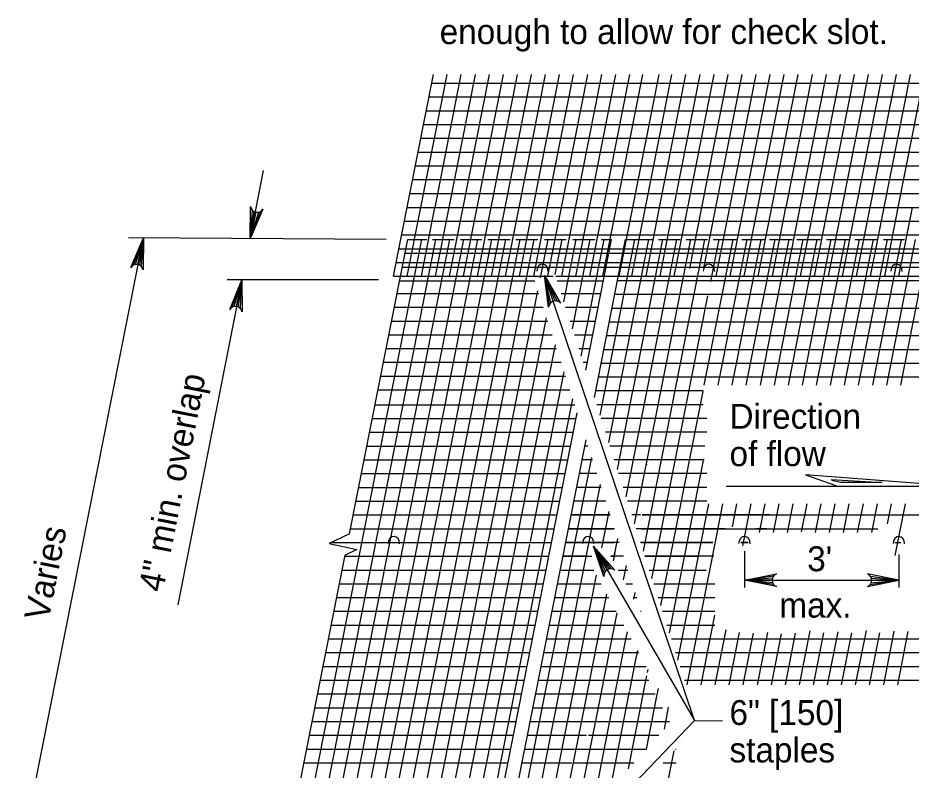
# Model space of a CAD drawing. Extents: x 1083.1 to 1117.1, y 719.4 to 741.4.
# Drawn here: x 1096.26 to 1101.28, y 728.46 to 732.68 of the extents above; entities that cross this region are included whole.
import ezdxf

# ---------------------------------------------------------------- set-up
doc = ezdxf.new("R2010")
doc.units = 0
doc.layers.add('ST_Details', color=7, linetype='Continuous')
doc.layers.add('ST_Text', color=7, linetype='Continuous')

msp = doc.modelspace()

# ---------------------------------------------------------------- linework, layer by layer
at = {"layer": 'ST_Details'}
for p, q in [((1098.3754, 731.2305), (1098.5998, 732.3652)), ((1098.5294, 731.6174), (1098.6773, 732.3652)), ((1098.6083, 731.6174), (1098.7562, 732.3652)), ((1098.6872, 731.6174), (1098.835, 732.3652)), ((1098.7661, 731.6174), (1098.9139, 732.3652)), ((1098.8449, 731.6174), (1098.9928, 732.3652)), ((1098.9238, 731.6174), (1099.0717, 732.3652)), ((1099.0027, 731.6174), (1099.1505, 732.3652)), ((1099.0816, 731.6174), (1099.2294, 732.3652)), ((1099.1604, 731.6174), (1099.3083, 732.3652)), ((1099.2393, 731.6174), (1099.3872, 732.3652)), ((1099.3183, 731.6174), (1099.4661, 732.3652)), ((1099.3971, 731.6174), (1099.5449, 732.3652)), ((1099.476, 731.6174), (1099.6238, 732.3652)), ((1099.5548, 731.6174), (1099.7027, 732.3652)), ((1099.6273, 731.6174), (1099.7752, 732.3652)), ((1099.7191, 731.6174), (1099.8669, 732.3652)), ((1099.7915, 731.6174), (1099.9394, 732.3652)), ((1099.8703, 731.6174), (1100.0183, 732.3652)), ((1099.9493, 731.6174), (1100.0971, 732.3652)), ((1100.0281, 731.6174), (1100.176, 732.3652)), ((1100.107, 731.6174), (1100.2548, 732.3652)), ((1100.1859, 731.6174), (1100.3338, 732.3652)), ((1100.2648, 731.6174), (1100.4126, 732.3652)), ((1100.3437, 731.6174), (1100.4915, 732.3652)), ((1100.4225, 731.6174), (1100.5703, 732.3652)), ((1100.5014, 731.6174), (1100.6493, 732.3652)), ((1100.5803, 731.6174), (1100.7282, 732.3652)), ((1100.6592, 731.6174), (1100.807, 732.3652)), ((1100.738, 731.6174), (1100.8859, 732.3652)), ((1100.8169, 731.6174), (1100.9648, 732.3652)), ((1100.8958, 731.6174), (1101.0437, 732.3652)), ((1100.9747, 731.6174), (1101.1225, 732.3652)), ((1101.0536, 731.6174), (1101.2014, 732.3652)), ((1101.1324, 731.6174), (1101.2803, 732.3652)), ((1101.2113, 731.6174), (1101.3592, 732.3652)), ((1101.9012, 732.3137), (1098.5898, 732.3137)), ((1101.8858, 732.2363), (1098.5745, 732.2363)), ((1101.8706, 732.159), (1098.5592, 732.159)), ((1101.8553, 732.0816), (1098.5439, 732.0816)), ((1101.8399, 732.0042), (1098.5286, 732.0042)), ((1101.8247, 731.9269), (1098.5133, 731.9269)), ((1101.8093, 731.8495), (1098.498, 731.8495)), ((1097.5708, 731.4497), (1097.645, 731.8248)), ((1101.7941, 731.7722), (1098.4827, 731.7722)), ((1101.7788, 731.6947), (1098.4673, 731.6947)), ((1097.5808, 731.6032), (1097.5693, 731.4418)), ((1098.4518, 731.6174), (1101.7633, 731.6174)), ((1098.452, 731.6174), (1099.6343, 731.6174)), ((1098.4528, 731.2305), (1098.5293, 731.6174)), ((1098.5317, 731.2305), (1098.6082, 731.6174)), ((1098.6106, 731.2305), (1098.687, 731.6174)), ((1098.6894, 731.2305), (1098.7659, 731.6174)), ((1098.7683, 731.2305), (1098.8448, 731.6174)), ((1098.8472, 731.2305), (1098.9237, 731.6174)), ((1098.9261, 731.2305), (1099.0025, 731.6174)), ((1099.0049, 731.2305), (1099.0814, 731.6174)), ((1099.0838, 731.2305), (1099.1603, 731.6174)), ((1099.1627, 731.2305), (1099.2392, 731.6174)), ((1099.2416, 731.2305), (1099.3181, 731.6174)), ((1099.3205, 731.2305), (1099.3969, 731.6174)), ((1099.3993, 731.2305), (1099.4758, 731.6174)), ((1099.4783, 731.2305), (1099.5547, 731.6174)), ((1099.5507, 731.2305), (1099.6272, 731.6174)), ((1099.6425, 731.2305), (1099.7189, 731.6174)), ((1099.7148, 731.2305), (1099.7913, 731.6174)), ((1099.7938, 731.2305), (1099.8702, 731.6174)), ((1099.8726, 731.2305), (1099.9491, 731.6174)), ((1099.9515, 731.2305), (1100.028, 731.6174)), ((1100.0392, 731.275), (1100.1068, 731.6174)), ((1100.1183, 731.2763), (1100.1858, 731.6174)), ((1100.1882, 731.2305), (1100.2646, 731.6174)), ((1100.267, 731.2305), (1100.3435, 731.6174)), ((1100.3459, 731.2305), (1100.4223, 731.6174)), ((1100.4248, 731.2305), (1100.5013, 731.6174)), ((1100.5037, 731.2305), (1100.5801, 731.6174)), ((1100.5825, 731.2305), (1100.659, 731.6174)), ((1100.6614, 731.2305), (1100.7378, 731.6174)), ((1100.7403, 731.2305), (1100.8168, 731.6174)), ((1100.8192, 731.2305), (1100.8957, 731.6174)), ((1100.8981, 731.2305), (1100.9745, 731.6174)), ((1100.9769, 731.2305), (1101.0534, 731.6174)), ((1101.0558, 731.2305), (1101.1323, 731.6174)), ((1101.1347, 731.2305), (1101.2112, 731.6174)), ((1101.2136, 731.2305), (1101.29, 731.6174)), ((1097.5905, 731.5956), (1097.5693, 731.4418)), ((1097.6273, 731.5952), (1097.5693, 731.4418)), ((1097.6013, 731.5916), (1097.5693, 731.4418)), ((1097.6159, 731.5913), (1097.5693, 731.4418)), ((1098.4365, 731.54), (1101.748, 731.54)), ((1098.4368, 731.54), (1099.6189, 731.54)), ((1096.2648, 727.8872), (1096.9698, 731.4464)), ((1098.3344, 731.4372), (1096.8864, 731.4464)), ((1096.9135, 731.2932), (1096.9712, 731.4467)), ((1096.9249, 731.2971), (1096.9712, 731.4467)), ((1096.9396, 731.2969), (1096.9712, 731.4467)), ((1096.9503, 731.2929), (1096.9712, 731.4467)), ((1096.96, 731.2853), (1096.9712, 731.4467)), ((1098.4213, 731.4627), (1101.7328, 731.4627)), ((1098.4214, 731.4627), (1099.6036, 731.4627)), ((1097.8295, 727.8781), (1098.5338, 731.4372)), ((1097.9083, 727.8781), (1098.6126, 731.4372)), ((1097.9873, 727.8781), (1098.6915, 731.4372)), ((1098.0662, 727.8781), (1098.7704, 731.4372)), ((1098.128, 729.7837), (1098.4548, 731.4372)), ((1098.145, 727.8781), (1098.8493, 731.4372)), ((1098.2239, 727.8781), (1098.9282, 731.4372)), ((1098.3028, 727.8781), (1099.007, 731.4372)), ((1098.3817, 727.8781), (1099.0859, 731.4372)), ((1098.4548, 731.4372), (1098.5617, 731.4372)), ((1098.4605, 727.8781), (1099.1648, 731.4372)), ((1098.5943, 731.4372), (1098.7153, 731.4372)), ((1098.7523, 731.4372), (1098.8722, 731.4372)), ((1098.906, 731.4372), (1099.031, 731.4372)), ((1099.0629, 731.4372), (1099.1868, 731.4372)), ((1099.2011, 731.2221), (1099.2437, 731.4372)), ((1099.2242, 731.4372), (1099.3446, 731.4372)), ((1099.2837, 731.2407), (1099.3225, 731.4372)), ((1099.3323, 731.088), (1099.4014, 731.4372)), ((1099.381, 730.9349), (1099.4803, 731.4372)), ((1099.3828, 731.4372), (1099.5073, 731.4372)), ((1099.4298, 730.7821), (1099.5592, 731.4372)), ((1099.4551, 730.7024), (1099.6003, 731.4372)), ((1099.5038, 730.5496), (1099.6792, 731.4372)), ((1099.5354, 730.45), (1099.7306, 731.4372)), ((1099.5416, 731.4372), (1099.6003, 731.4372)), ((1099.5841, 730.2972), (1099.8095, 731.4372)), ((1099.6792, 731.4372), (1099.8299, 731.4372)), ((1099.6814, 729.9917), (1099.9673, 731.4372)), ((1099.7191, 730.5807), (1099.8884, 731.4372)), ((1099.8635, 731.4372), (1099.9853, 731.4372)), ((1099.9089, 730.7417), (1100.0462, 731.4372)), ((1100.019, 731.4372), (1100.1399, 731.4372)), ((1100.09, 731.2597), (1100.1251, 731.4372)), ((1100.1208, 730.618), (1100.2827, 731.4372)), ((1100.1573, 731.2008), (1100.204, 731.4372)), ((1100.171, 731.4372), (1100.3024, 731.4372)), ((1100.1996, 730.618), (1100.3616, 731.4372)), ((1100.2785, 730.618), (1100.4404, 731.4372)), ((1100.3327, 731.4372), (1100.4604, 731.4372)), ((1100.3573, 730.618), (1100.5193, 731.4372)), ((1100.4363, 730.618), (1100.5982, 731.4372)), ((1100.4881, 731.4372), (1100.6176, 731.4372)), ((1100.5151, 730.618), (1100.6771, 731.4372)), ((1100.5941, 730.618), (1100.7559, 731.4372)), ((1100.6409, 731.4372), (1100.7742, 731.4372)), ((1100.6729, 730.618), (1100.8348, 731.4372)), ((1100.7518, 730.618), (1100.9137, 731.4372)), ((1100.8069, 731.4372), (1100.9337, 731.4372)), ((1100.8307, 730.618), (1100.9926, 731.4372)), ((1100.9095, 730.618), (1101.0715, 731.4372)), ((1100.967, 731.4372), (1101.0923, 731.4372)), ((1100.9884, 730.618), (1101.1503, 731.4372)), ((1101.0673, 730.618), (1101.2293, 731.4372)), ((1101.1273, 731.4372), (1101.2462, 731.4372)), ((1101.1462, 730.618), (1101.3081, 731.4372)), ((1101.225, 730.618), (1101.387, 731.4372)), ((1098.406, 731.3852), (1101.7174, 731.3852)), ((1098.4061, 731.3852), (1099.5883, 731.3852)), ((1098.4395, 731.3598), (1102.2394, 731.3598)), ((1098.3908, 731.3079), (1099.5729, 731.3079)), ((1098.3908, 731.3079), (1101.7022, 731.3079)), ((1098.4243, 731.2825), (1102.2241, 731.2825)), ((1099.7788, 729.6857), (1100.0908, 731.2637)), ((1097.5238, 731.2114), (1097.1626, 729.3849)), ((1098.2907, 731.2114), (1097.4404, 731.2114)), ((1097.468, 731.0572), (1097.5238, 731.2114)), ((1097.4793, 731.0612), (1097.5238, 731.2114)), ((1097.494, 731.0612), (1097.5238, 731.2114)), ((1097.5048, 731.0574), (1097.5238, 731.2114)), ((1097.5147, 731.0499), (1097.5238, 731.2114)), ((1098.3754, 731.2305), (1099.2724, 731.2305)), ((1098.409, 731.2052), (1099.1688, 731.2052)), ((1100.0671, 728.734), (1099.2233, 731.2357)), ((1099.2725, 731.0907), (1099.2233, 731.2357)), ((1099.2598, 731.0834), (1099.2233, 731.2357)), ((1099.2519, 731.0742), (1099.2233, 731.2357)), ((1099.2838, 731.0927), (1099.2233, 731.2357)), ((1099.296, 731.0912), (1099.2233, 731.2357)), ((1099.2869, 731.2305), (1101.7658, 731.2305)), ((1099.295, 731.2052), (1099.5549, 731.2052)), ((1100.1537, 731.2052), (1099.6333, 731.2052)), ((1102.2088, 731.2052), (1100.1558, 731.2052)), ((1098.5394, 727.8781), (1099.1867, 731.1494)), ((1098.395, 731.1341), (1099.1917, 731.1341)), ((1099.3177, 731.1341), (1099.5404, 731.1341)), ((1099.5404, 731.1341), (1099.5404, 731.1341)), ((1100.1454, 731.1277), (1099.618, 731.1277)), ((1099.8274, 729.5331), (1100.1413, 731.1202)), ((1102.1935, 731.1277), (1100.1454, 731.1277)), ((1098.3797, 731.0567), (1099.2166, 731.0567)), ((1099.3423, 731.0567), (1099.5252, 731.0567)), ((1100.0889, 731.0504), (1099.6027, 731.0504)), ((1102.1782, 731.0504), (1100.0889, 731.0504)), ((1098.6183, 727.8781), (1099.2356, 730.9977)), ((1099.8875, 731.0337), (1099.8875, 731.0338)), ((1098.3643, 730.9793), (1099.2415, 730.9793)), ((1099.3669, 730.9793), (1099.5098, 730.9793)), ((1100.0408, 730.973), (1099.5873, 730.973)), ((1102.1629, 730.973), (1100.0408, 730.973)), ((1098.3491, 730.902), (1099.2664, 730.902)), ((1099.3916, 730.902), (1099.4946, 730.902)), ((1099.9951, 730.8957), (1099.572, 730.8957)), ((1102.1477, 730.8957), (1099.9951, 730.8957)), ((1098.6972, 727.8781), (1099.2844, 730.846)), ((1098.3338, 730.8246), (1099.2913, 730.8246)), ((1099.4162, 730.8246), (1099.4793, 730.8246)), ((1099.9553, 730.8182), (1099.5567, 730.8182)), ((1102.1323, 730.8182), (1099.9553, 730.8182)), ((1098.3184, 730.7472), (1099.3163, 730.7472)), ((1099.4408, 730.7472), (1099.464, 730.7472)), ((1099.1449, 729.7403), (1099.3334, 730.6939)), ((1099.9133, 730.7409), (1099.5413, 730.7409)), ((1099.7299, 729.8391), (1099.9087, 730.7418)), ((1102.1171, 730.7409), (1099.9133, 730.7409)), ((1098.3032, 730.6698), (1099.3412, 730.6698)), ((1099.8838, 730.6635), (1099.526, 730.6635)), ((1102.1018, 730.6635), (1099.8838, 730.6635)), ((1098.2878, 730.5925), (1099.3661, 730.5925)), ((1099.8632, 730.5862), (1099.5107, 730.5862)), ((1099.6328, 730.1443), (1099.7201, 730.5862)), ((1100.1141, 730.5862), (1099.8632, 730.5862)), ((1099.8761, 729.3802), (1100.1141, 730.5842)), ((1098.2715, 730.5087), (1099.393, 730.5087)), ((1098.8558, 727.8781), (1099.3823, 730.5421)), ((1099.8447, 730.5087), (1099.5168, 730.5087)), ((1100.1141, 730.5087), (1099.8447, 730.5087)), ((1098.8968, 727.8781), (1099.4078, 730.4631)), ((1098.2563, 730.4314), (1099.4018, 730.4314)), ((1099.8212, 730.4314), (1099.5413, 730.4314)), ((1100.135, 730.4314), (1099.8212, 730.4314)), ((1098.2409, 730.354), (1099.3864, 730.354)), ((1099.8035, 730.354), (1099.566, 730.354)), ((1100.135, 730.354), (1099.8035, 730.354)), ((1098.9756, 727.8781), (1099.4567, 730.3113)), ((1098.2256, 730.2767), (1099.3711, 730.2767)), ((1099.4678, 730.2767), (1099.4494, 730.2767)), ((1099.7929, 730.2767), (1099.5907, 730.2767)), ((1100.1236, 730.2767), (1099.7929, 730.2767)), ((1098.2103, 730.1992), (1099.3558, 730.1992)), ((1099.0271, 727.8781), (1099.4885, 730.2124)), ((1099.4927, 730.1992), (1099.4341, 730.1992)), ((1099.7823, 730.1992), (1099.6153, 730.1992)), ((1100.1199, 730.1992), (1099.7823, 730.1992)), ((1099.9248, 729.2274), (1100.1179, 730.2045)), ((1099.7953, 730.1752), (1099.8002, 730.1752)), ((1098.1949, 730.1219), (1099.3404, 730.1219)), ((1099.5176, 730.1219), (1099.4188, 730.1219)), ((1099.7739, 730.1219), (1099.6399, 730.1219)), ((1100.135, 730.1219), (1099.7739, 730.1219)), ((1101.5129, 730.0519), (1100.6896, 730.1146)), ((1100.6896, 730.1146), (1100.8608, 730.0545)), ((1098.1796, 730.0446), (1099.3251, 730.0446)), ((1099.106, 727.8781), (1099.5373, 730.0606)), ((1099.5426, 730.0446), (1099.4034, 730.0446)), ((1099.7759, 730.0446), (1099.6646, 730.0446)), ((1100.135, 730.0446), (1099.7759, 730.0446)), ((1100.2433, 730.0519), (1101.5129, 730.0519)), ((1100.8334, 730.0884), (1101.1211, 730.0727)), ((1100.8879, 730.0727), (1100.8384, 730.0832)), ((1101.1211, 730.0727), (1100.8879, 730.0727)), ((1098.1643, 729.9672), (1099.3098, 729.9672)), ((1099.5675, 729.9672), (1099.3881, 729.9672)), ((1099.7853, 729.9672), (1099.6892, 729.9672)), ((1100.135, 729.9672), (1099.7853, 729.9672)), ((1100.0893, 729.6607), (1100.1471, 729.953)), ((1100.1855, 729.7485), (1100.2259, 729.953)), ((1100.2792, 729.8233), (1100.3048, 729.953)), ((1100.337, 729.7162), (1100.3838, 729.953)), ((1100.4307, 729.7917), (1100.4626, 729.953)), ((1100.5096, 729.7917), (1100.5415, 729.953)), ((1100.5884, 729.7917), (1100.6203, 729.953)), ((1100.668, 729.795), (1100.6993, 729.953)), ((1100.7462, 729.7917), (1100.7781, 729.953)), ((1100.8251, 729.7917), (1100.857, 729.953)), ((1100.904, 729.7917), (1100.9358, 729.9526)), ((1100.9828, 729.7917), (1101.0148, 729.953)), ((1101.0618, 729.7917), (1101.0936, 729.953)), ((1101.15, 729.8394), (1101.1725, 729.953)), ((1101.1938, 729.6619), (1101.2513, 729.953)), ((1099.5458, 729.7047), (1099.5863, 729.9089)), ((1098.149, 729.8898), (1099.2946, 729.8898)), ((1099.5924, 729.8898), (1099.3728, 729.8898)), ((1099.3733, 729.8898), (1099.5924, 729.8898)), ((1099.762, 729.8898), (1099.7138, 729.8898)), ((1100.4879, 729.8898), (1099.7717, 729.8898)), ((1099.7717, 729.8898), (1101.9488, 729.8898)), ((1098.1337, 729.8124), (1099.2793, 729.8124)), ((1099.6173, 729.8124), (1099.3574, 729.8124)), ((1099.358, 729.8124), (1099.6113, 729.8124)), ((1099.7655, 729.8124), (1099.7384, 729.8124)), ((1100.2388, 729.8124), (1099.7655, 729.8124)), ((1099.7655, 729.8124), (1101.0968, 729.8124)), ((1100.4726, 729.8124), (1100.4099, 729.8124)), ((1098.128, 729.7837), (1098.0141, 729.7285)), ((1099.6155, 729.6583), (1099.6351, 729.7573)), ((1100.0248, 728.9353), (1100.1873, 729.7579)), ((1098.0141, 729.7285), (1098.1687, 729.6947)), ((1098.0277, 729.7351), (1099.2634, 729.7351)), ((1098.1687, 729.6947), (1098.1043, 729.6635)), ((1098.7761, 727.8781), (1099.1417, 729.7239)), ((1099.5544, 729.7351), (1099.3421, 729.7351)), ((1099.3427, 729.7351), (1099.6162, 729.7351)), ((1099.4994, 729.7143), (1100.0671, 728.734)), ((1099.5763, 729.5818), (1099.4994, 729.7143)), ((1099.5653, 729.5722), (1099.4994, 729.7143)), ((1099.5593, 729.5617), (1099.4994, 729.7143)), ((1099.5869, 729.5861), (1099.4994, 729.7143)), ((1099.5993, 729.587), (1099.4994, 729.7143)), ((1099.6423, 729.7351), (1099.5544, 729.7351)), ((1099.7667, 729.7351), (1099.7631, 729.7351)), ((1100.17, 729.7351), (1099.7667, 729.7351)), ((1099.7667, 729.7351), (1100.17, 729.7351)), ((1100.365, 729.7351), (1100.326, 729.7351)), ((1100.326, 729.7351), (1100.3671, 729.7351)), ((1101.1912, 729.7351), (1101.2254, 729.7351)), ((1097.7506, 727.8781), (1098.1043, 729.6635)), ((1098.1031, 729.6577), (1099.2487, 729.6577)), ((1099.4578, 729.6577), (1099.3268, 729.6577)), ((1099.3274, 729.6577), (1099.4578, 729.6577)), ((1099.4627, 729.6577), (1099.4578, 729.6577)), ((1099.4578, 729.6577), (1099.4893, 729.6577)), ((1099.5351, 729.6504), (1099.5358, 729.6538)), ((1099.6672, 729.6577), (1099.5961, 729.6577)), ((1099.5961, 729.6577), (1099.6186, 729.6577)), ((1099.6103, 729.6314), (1099.6198, 729.6792)), ((1099.6198, 729.6792), (1099.6198, 729.6793)), ((1100.174, 729.6577), (1099.7878, 729.6577)), ((1099.7878, 729.6577), (1100.0862, 729.6577)), ((1099.9734, 729.0745), (1100.0887, 729.6572)), ((1100.3465, 729.6871), (1100.3465, 729.4812)), ((1101.2144, 729.6677), (1101.2144, 729.4812)), ((1099.6678, 729.5248), (1099.6838, 729.606)), ((1098.0878, 729.5803), (1099.2333, 729.5803)), ((1099.2303, 728.1086), (1099.5156, 729.5517)), ((1099.3122, 729.5803), (1099.4999, 729.5803)), ((1099.6378, 729.5803), (1099.6921, 729.5803)), ((1099.8123, 729.5803), (1100.1324, 729.5803)), ((1100.5096, 729.5453), (1100.3493, 729.5229)), ((1101.0543, 729.5453), (1101.2145, 729.5229)), ((1098.0725, 729.5029), (1099.218, 729.5029)), ((1099.2968, 729.5029), (1099.5422, 729.5029)), ((1099.6795, 729.5029), (1099.717, 729.5029)), ((1099.837, 729.5029), (1099.9163, 729.5029)), ((1099.9169, 729.5029), (1100.1811, 729.5029)), ((1100.3465, 729.5229), (1101.2145, 729.5229)), ((1100.5042, 729.5342), (1100.3493, 729.5229)), ((1100.5025, 729.5229), (1100.3493, 729.5229)), ((1100.5053, 729.5085), (1100.3493, 729.5229)), ((1100.5115, 729.4982), (1100.3493, 729.5229)), ((1101.0523, 729.4982), (1101.2145, 729.5229)), ((1101.0585, 729.5085), (1101.2145, 729.5229)), ((1101.0597, 729.5342), (1101.2145, 729.5229)), ((1101.0613, 729.5229), (1101.2145, 729.5229)), ((1099.4456, 728.7984), (1099.5735, 729.4455)), ((1099.7258, 729.4172), (1099.7329, 729.4535)), ((1098.0572, 729.4256), (1099.2027, 729.4256)), ((1099.2816, 729.4256), (1099.5844, 729.4256)), ((1099.7213, 729.4256), (1099.7419, 729.4256)), ((1099.8617, 729.4256), (1100.1811, 729.4256)), ((1098.0418, 729.3482), (1099.1873, 729.3482)), ((1099.2663, 729.3482), (1099.6267, 729.3482)), ((1099.5377, 728.8656), (1099.6313, 729.3395)), ((1099.614, 729.2537), (1099.6311, 729.34)), ((1099.763, 729.3482), (1099.7668, 729.3482)), ((1099.8863, 729.3482), (1099.8905, 729.3482)), ((1099.8905, 729.3482), (1100.1811, 729.3482)), ((1100.1037, 728.9353), (1100.1811, 729.3269)), ((1098.0265, 729.2708), (1099.172, 729.2708)), ((1099.2509, 729.2708), (1099.6639, 729.2708)), ((1099.6637, 729.2708), (1099.6688, 729.2708)), ((1099.9109, 729.2708), (1100.1811, 729.2708)), ((1100.1827, 728.9353), (1100.2437, 729.2443)), ((1100.6559, 728.9353), (1100.7158, 729.2393)), ((1100.9713, 728.9353), (1101.0316, 729.2399)), ((1098.0112, 729.1934), (1099.1567, 729.1934)), ((1099.2357, 729.1934), (1099.7111, 729.1934)), ((1099.6212, 728.8887), (1099.6864, 729.2189)), ((1099.684, 729.2063), (1099.6893, 729.2332)), ((1099.9364, 729.1934), (1101.2275, 729.1934)), ((1100.2614, 728.9353), (1100.3195, 729.2292)), ((1100.3403, 728.9353), (1100.3977, 729.2258)), ((1100.4192, 728.9353), (1100.4773, 729.2294)), ((1100.4981, 728.9353), (1100.5546, 729.2223)), ((1100.5769, 728.9353), (1100.6342, 729.2248)), ((1100.7347, 728.9353), (1100.7926, 729.228)), ((1100.8136, 728.9353), (1100.8726, 729.2336)), ((1100.8925, 728.9353), (1100.95, 729.2274)), ((1101.0502, 728.9353), (1101.1077, 729.2272)), ((1101.1291, 728.9353), (1101.1887, 729.2362)), ((1101.1876, 729.2311), (1101.1883, 729.2344)), ((1101.1876, 729.1934), (1101.8112, 729.1934)), ((1101.2079, 728.9353), (1101.267, 729.2344)), ((1097.9958, 729.1161), (1099.1413, 729.1161)), ((1099.2203, 729.1161), (1099.7533, 729.1161)), ((1099.7364, 729.0732), (1099.7472, 729.1273)), ((1099.9602, 729.1161), (1100.0258, 729.1161)), ((1099.9602, 729.1161), (1101.2172, 729.1161)), ((1101.1876, 729.1161), (1101.7958, 729.1161)), ((1097.9805, 729.0387), (1099.1261, 729.0387)), ((1099.205, 729.0387), (1099.7617, 729.0387)), ((1099.6599, 729.0387), (1099.7955, 729.0387)), ((1099.7029, 728.9035), (1099.7393, 729.0877)), ((1099.9848, 729.0387), (1101.2172, 729.0387)), ((1101.1876, 729.0387), (1101.7806, 729.0387)), ((1099.8018, 729.0038), (1099.8052, 729.0211)), ((1097.9652, 728.9613), (1099.1108, 728.9613)), ((1099.1898, 728.9613), (1099.8095, 728.9613)), ((1099.7803, 728.8953), (1099.7981, 728.9856)), ((1100.0094, 728.9613), (1101.7653, 728.9613)), ((1099.5938, 728.3509), (1099.7019, 728.8982)), ((1099.6948, 728.4627), (1099.783, 728.9092)), ((1099.8512, 728.8552), (1099.863, 728.9151)), ((1097.9498, 728.884), (1099.0954, 728.884)), ((1099.1744, 728.884), (1099.8451, 728.884)), ((1099.3918, 728.1272), (1099.5393, 728.8734)), ((1099.4928, 728.2392), (1099.6202, 728.8837)), ((1099.7958, 728.5746), (1099.8527, 728.8627)), ((1097.9345, 728.8066), (1099.0801, 728.8066)), ((1099.1592, 728.8066), (1099.8867, 728.8066)), ((1099.2909, 728.0156), (1099.4496, 728.8163)), ((1099.9047, 728.7267), (1099.9209, 728.809)), ((1099.8967, 728.6864), (1099.9069, 728.7382)), ((1097.9192, 728.7292), (1099.0648, 728.7292)), ((1099.1439, 728.7292), (1099.5692, 728.7292)), ((1100.0671, 728.734), (1099.3303, 727.9711)), ((1099.5723, 728.7292), (1099.9252, 728.7292)), ((1100.0671, 728.734), (1100.2231, 728.733)), ((1097.9039, 728.6518), (1099.0494, 728.6518)), ((1099.1286, 728.6518), (1099.4596, 728.6518)), ((1099.4715, 728.6518), (1099.8655, 728.6518)), ((1097.8886, 728.5745), (1099.0341, 728.5745)), ((1099.1133, 728.5745), (1099.4256, 728.5745)), ((1099.4253, 728.5745), (1099.7956, 728.5745)), ((1099.8158, 727.8781), (1099.9516, 728.5652)), ((1099.96, 728.5745), (1099.9634, 728.5745)), ((1097.8733, 728.4971), (1099.0188, 728.4971)), ((1099.098, 728.4971), (1099.3764, 728.4971)), ((1099.384, 728.4971), (1099.7258, 728.4971)), ((1099.8894, 728.4971), (1099.9634, 728.4971))]:
    msp.add_line(p, q, dxfattribs=at)
for points in [[(1097.6408, 731.6075), (1097.5693, 731.4418), (1097.5716, 731.6222)], [(1096.9, 731.2808), (1096.9712, 731.4467), (1096.9693, 731.2662)], [(1097.4547, 731.0447), (1097.5238, 731.2114), (1097.5241, 731.0309)], [(1099.2467, 731.0567), (1099.2233, 731.2357), (1099.3138, 731.0795)], [(1099.5577, 729.5435), (1099.4994, 729.7143), (1099.6189, 729.579)], [(1100.5263, 729.4875), (1100.3493, 729.5229), (1100.5263, 729.5583)], [(1101.0375, 729.4875), (1101.2145, 729.5229), (1101.0375, 729.5583)], [(1099.7726, 729.3303), (1099.7726, 729.3303)]]:
    msp.add_lwpolyline(points, dxfattribs=at)
for centre, start, end in [((1097.6092, 731.6289), 190.0563, 325.8824), ((1096.9317, 731.2595), 10.1811, 146.0073), ((1097.4867, 731.0238), 10.905, 146.7312), ((1099.2848, 731.0546), 40.8204, 176.6465), ((1099.5955, 729.5489), 52.2231, 188.0492), ((1100.5407, 729.523), 112.0878, 247.9139), ((1101.0232, 729.523), 292.0861, 67.9122)]:
    msp.add_arc(centre, 0.0382, start, end, dxfattribs=at)
for centre in [(1099.2122, 731.2581), (1100.1472, 731.2581), (1101.2013, 731.2581), (1098.3771, 729.7283), (1099.4689, 729.7283), (1100.346, 729.7283), (1101.214, 729.7283)]:
    msp.add_ellipse(centre, major_axis=(0.001, 0.041), ratio=0.78812, start_param=4.7124, end_param=7.853992, dxfattribs=at)

# ---------------------------------------------------------------- texts
at = {"layer": 'ST_Text'}
for s, p in [('enough to allow for check slot.', (1098.6344, 732.5352)), ('Direction', (1100.263, 730.3739)), ('of flow', (1100.263, 730.1639)), ("3'", (1100.6993, 729.5734)), ('max.', (1100.5427, 729.3129)), ('6" [150]', (1100.2627, 728.7092)), ('staples', (1100.2627, 728.4992))]:
    msp.add_text(s, height=0.14, dxfattribs=at).set_placement(p)
for s, p in [('4" min. overlap', (1097.0793, 729.4506)), ('Varies', (1096.437, 729.2905))]:
    msp.add_text(s, height=0.14, rotation=78.8192, dxfattribs=at).set_placement(p)

doc.saveas('drawing.dxf')
